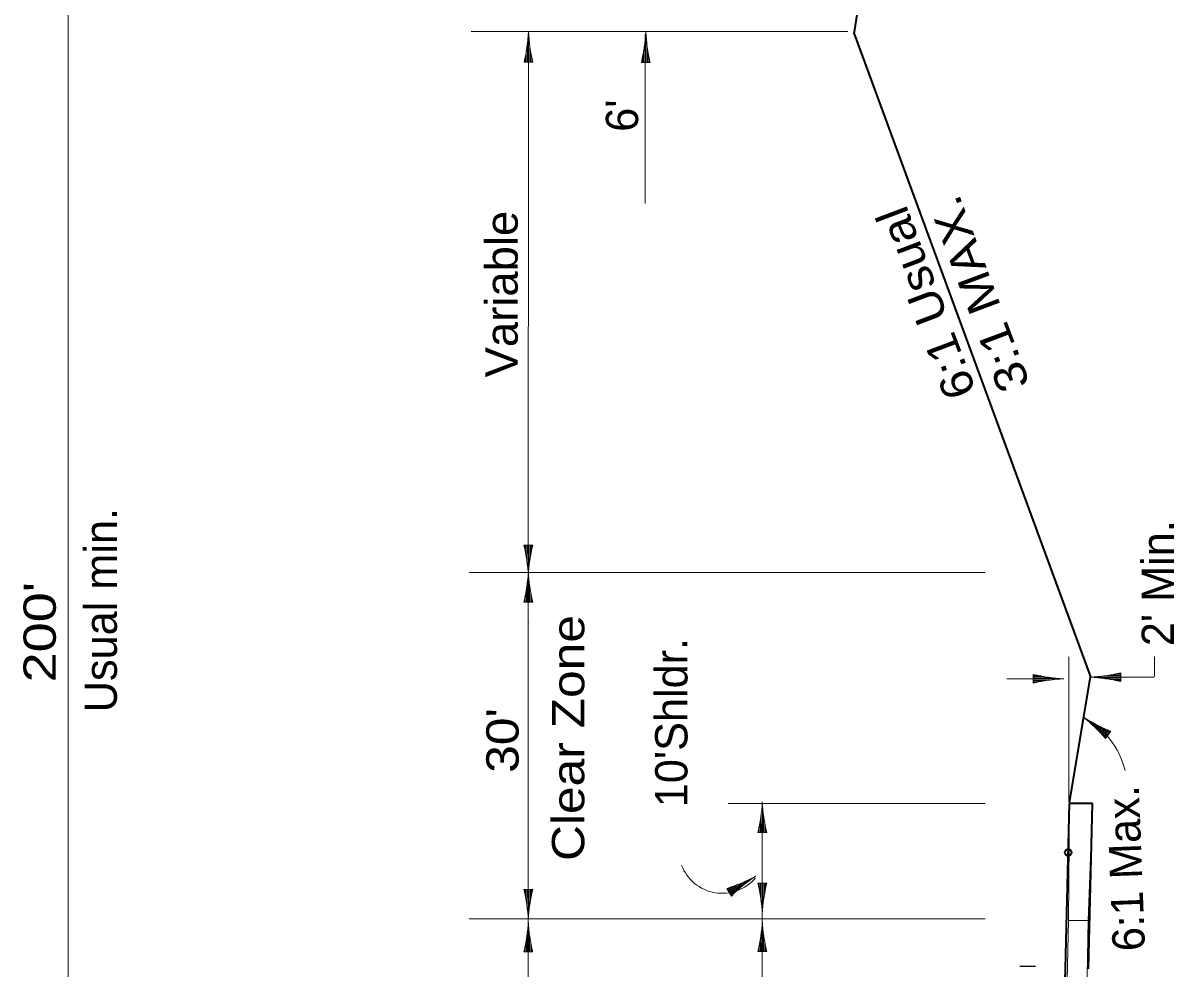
# Model space of a CAD drawing. Extents: x 2363427 to 2368559, y 6957299 to 6980140.
# Drawn here: x 2363668.7 to 2364167.1, y 6961810.7 to 6962220.2 of the extents above; entities that cross this region are included whole.
import ezdxf
from ezdxf.enums import TextEntityAlignment as Align

# ---------------------------------------------------------------- set-up
doc = ezdxf.new("R2010")
doc.units = 0
doc.header["$LTSCALE"] = 5.6
doc.header["$PDMODE"] = 32
doc.header["$PDSIZE"] = 2.8
for name, color, linetype, lineweight in [('3', 7, 'Continuous', 35), ('4', 7, 'Continuous', 13), ('48', 7, 'Continuous', 25)]:
    doc.layers.add(name, color=color, linetype=linetype, lineweight=lineweight)

msp = doc.modelspace()

# ---------------------------------------------------------------- linework, layer by layer
at = {"layer": '3'}
for p, q in [((2364028.519, 6962215.437), (2364033.505, 6962246.281)), ((2364028.519, 6962215.437), (2364130.866, 6961937.19)), ((2364121.845, 6961882.668), (2364130.866, 6961937.19)), ((2364120.086, 6961810.917), (2364121.751, 6961882.347)), ((2364131.755, 6961882.347), (2364121.751, 6961882.347)), ((2364130.083, 6961810.683), (2364131.752, 6961882.231)), ((2364121.017, 6961860.969), (2364121.255, 6961861.068))]:
    msp.add_line(p, q, dxfattribs=at)
at = {"layer": '3', "lineweight": 13}
msp.add_lwpolyline([(2364121.322, 6961831.721), (2364129.856, 6961831.721), (2364131.755, 6961882.347), (2364121.751, 6961882.347)], close=True, dxfattribs=at)
at = {"layer": '3'}
msp.add_lwpolyline([(2364111.676, 6961377.102), (2364116.953, 6961691.051), (2364120.086, 6961810.917)], dxfattribs=at)
msp.add_point((2364121.255, 6961861.068), dxfattribs=at)
at = {"layer": '4'}
for p, q in [((2363688.134, 6961377.102), (2363688.134, 6962511.097)), ((2364025.901, 6962216.508), (2363862.717, 6962216.508)), ((2363887.459, 6961961.097), (2363887.535, 6962216.508)), ((2363887.596, 6962203.196), (2363887.6, 6962215.76)), ((2363887.596, 6962203.196), (2363887.6, 6962215.76)), ((2363938.134, 6962142.008), (2363938.134, 6962215.267)), ((2363938.393, 6962203.111), (2363938.393, 6962215.675)), ((2363886.596, 6962203.196), (2363886.597, 6962208.058)), ((2363886.596, 6962203.196), (2363886.597, 6962208.058)), ((2363887.096, 6962203.196), (2363887.099, 6962211.806)), ((2363887.096, 6962203.196), (2363887.099, 6962211.806)), ((2363888.096, 6962203.196), (2363888.099, 6962210.546)), ((2363888.096, 6962203.196), (2363888.099, 6962210.546)), ((2363888.596, 6962203.196), (2363888.597, 6962207.472)), ((2363888.596, 6962203.196), (2363888.597, 6962207.472)), ((2363937.393, 6962203.111), (2363937.393, 6962207.973)), ((2363937.893, 6962203.111), (2363937.893, 6962211.72)), ((2363938.893, 6962203.111), (2363938.893, 6962210.461)), ((2363939.393, 6962203.111), (2363939.393, 6962207.387)), ((2363889.446, 6962203.196), (2363885.616, 6962203.196)), ((2363889.446, 6962203.196), (2363885.616, 6962203.196)), ((2363886.096, 6962203.196), (2363886.097, 6962205.578)), ((2363886.096, 6962203.196), (2363886.097, 6962205.578)), ((2363889.096, 6962203.196), (2363889.097, 6962204.78)), ((2363889.096, 6962203.196), (2363889.097, 6962204.78)), ((2363940.243, 6962203.111), (2363936.413, 6962203.111)), ((2363936.893, 6962203.111), (2363936.893, 6962205.492)), ((2363939.893, 6962203.111), (2363939.893, 6962204.695)), ((2363885.547, 6961994.152), (2363889.377, 6961994.151)), ((2363885.897, 6961994.152), (2363885.897, 6961992.567)), ((2363886.397, 6961994.152), (2363886.396, 6961989.875)), ((2363886.897, 6961994.151), (2363886.895, 6961986.802)), ((2363887.397, 6961994.151), (2363887.393, 6961981.587)), ((2363887.897, 6961994.151), (2363887.895, 6961985.541)), ((2363888.397, 6961994.151), (2363888.396, 6961989.289)), ((2363888.897, 6961994.151), (2363888.897, 6961991.769)), ((2364085.251, 6961982.347), (2363861.855, 6961982.347)), ((2363887.023, 6961969.513), (2363887.023, 6961978.122)), ((2363887.523, 6961969.513), (2363887.523, 6961982.077)), ((2363886.523, 6961969.513), (2363886.523, 6961974.375)), ((2363888.023, 6961969.513), (2363888.023, 6961976.863)), ((2363888.523, 6961969.513), (2363888.523, 6961973.789)), ((2363889.373, 6961969.513), (2363885.543, 6961969.513)), ((2363886.023, 6961969.513), (2363886.023, 6961971.894)), ((2363889.023, 6961969.513), (2363889.023, 6961971.097)), ((2363887.536, 6961960.669), (2363887.459, 6961961.097)), ((2364121.589, 6961882.873), (2364121.589, 6961945.809)), ((2364158.594, 6961937.315), (2364158.594, 6961945.959)), ((2364106.057, 6961934.384), (2364106.057, 6961938.214)), ((2364106.057, 6961934.384), (2364106.057, 6961938.214)), ((2364106.057, 6961937.734), (2364108.439, 6961937.734)), ((2364106.057, 6961937.734), (2364108.439, 6961937.734)), ((2364144.063, 6961938.031), (2364139.787, 6961938.031)), ((2364144.063, 6961938.531), (2364142.479, 6961938.531)), ((2364144.063, 6961938.881), (2364144.063, 6961935.051)), ((2364119.369, 6961936.299), (2364094.666, 6961936.299)), ((2364106.057, 6961937.234), (2364110.919, 6961937.234)), ((2364106.057, 6961937.234), (2364110.919, 6961937.234)), ((2364106.057, 6961936.734), (2364114.667, 6961936.734)), ((2364106.057, 6961936.734), (2364114.667, 6961936.734)), ((2364106.057, 6961936.234), (2364118.621, 6961936.234)), ((2364106.057, 6961936.234), (2364118.621, 6961936.234)), ((2364106.057, 6961935.734), (2364113.407, 6961935.734)), ((2364106.057, 6961935.734), (2364113.407, 6961935.734)), ((2364106.057, 6961935.234), (2364110.334, 6961935.234)), ((2364106.057, 6961935.234), (2364110.334, 6961935.234)), ((2364106.057, 6961934.734), (2364107.643, 6961934.734)), ((2364106.057, 6961934.734), (2364107.643, 6961934.734)), ((2364144.063, 6961937.031), (2364131.499, 6961937.031)), ((2364131.931, 6961936.967), (2364158.509, 6961936.967)), ((2364144.063, 6961936.531), (2364135.454, 6961936.531)), ((2364144.063, 6961937.531), (2364136.713, 6961937.531)), ((2364144.063, 6961936.031), (2364139.201, 6961936.031)), ((2364144.063, 6961935.531), (2364141.682, 6961935.531)), ((2364138.597, 6961912.088), (2364128.355, 6961919.367)), ((2364138.307, 6961911.681), (2364131.289, 6961916.669)), ((2364138.886, 6961912.495), (2364132.895, 6961916.753)), ((2364138.017, 6961911.273), (2364134.054, 6961914.089)), ((2364139.175, 6961912.903), (2364135.691, 6961915.381)), ((2364139.668, 6961913.596), (2364137.449, 6961910.474)), ((2364139.465, 6961913.311), (2364138.173, 6961914.229)), ((2364137.727, 6961910.865), (2364135.786, 6961912.245)), ((2364085.251, 6961882.347), (2363973.971, 6961882.347)), ((2363988.341, 6961869.718), (2363988.341, 6961878.327)), ((2363988.841, 6961869.718), (2363988.841, 6961882.282)), ((2363987.841, 6961869.718), (2363987.841, 6961874.58)), ((2363988.775, 6961823.369), (2363988.775, 6961873.397)), ((2363989.341, 6961869.718), (2363989.341, 6961877.068)), ((2363989.841, 6961869.718), (2363989.841, 6961873.995)), ((2363990.691, 6961869.718), (2363986.861, 6961869.718)), ((2363987.341, 6961869.718), (2363987.341, 6961872.099)), ((2363990.341, 6961869.718), (2363990.341, 6961871.303)), ((2363974.207, 6961844.261), (2363981.567, 6961848.729)), ((2363974.467, 6961843.834), (2363985.207, 6961850.353)), ((2363885.547, 6961845.139), (2363889.377, 6961845.137)), ((2363885.897, 6961845.139), (2363885.897, 6961843.553)), ((2363886.397, 6961845.139), (2363886.396, 6961840.862)), ((2363886.897, 6961845.138), (2363886.895, 6961837.789)), ((2363887.397, 6961845.138), (2363887.393, 6961832.574)), ((2363887.897, 6961845.138), (2363887.895, 6961836.528)), ((2363888.397, 6961845.138), (2363888.396, 6961840.276)), ((2363888.897, 6961845.137), (2363888.897, 6961842.756)), ((2363975.427, 6961842.253), (2363973.439, 6961845.527)), ((2363973.689, 6961845.116), (2363975.725, 6961846.352)), ((2363973.949, 6961844.689), (2363978.105, 6961847.211)), ((2363974.727, 6961843.407), (2363981.009, 6961847.221)), ((2363974.986, 6961842.979), (2363978.642, 6961845.198)), ((2363975.245, 6961842.552), (2363976.601, 6961843.375)), ((2363986.861, 6961847.809), (2363990.691, 6961847.809)), ((2363987.211, 6961847.809), (2363987.211, 6961846.223)), ((2363987.711, 6961847.809), (2363987.711, 6961843.532)), ((2363988.211, 6961847.809), (2363988.211, 6961840.459)), ((2363988.711, 6961847.809), (2363988.711, 6961835.245)), ((2363989.211, 6961847.809), (2363989.211, 6961839.199)), ((2363989.711, 6961847.809), (2363989.711, 6961842.947)), ((2363990.211, 6961847.809), (2363990.211, 6961845.427)), ((2364085.251, 6961832.347), (2363861.855, 6961832.347)), ((2363887.523, 6961818.035), (2363887.523, 6961830.599)), ((2363988.841, 6961818.195), (2363988.841, 6961830.759)), ((2363887.023, 6961818.035), (2363887.023, 6961826.644)), ((2363888.023, 6961818.035), (2363888.023, 6961825.385)), ((2363988.341, 6961818.195), (2363988.341, 6961826.804)), ((2363989.341, 6961818.195), (2363989.341, 6961825.545)), ((2363886.023, 6961818.035), (2363886.023, 6961820.416)), ((2363886.523, 6961818.035), (2363886.523, 6961822.897)), ((2363888.523, 6961818.035), (2363888.523, 6961822.311)), ((2363889.023, 6961818.035), (2363889.023, 6961819.619)), ((2363990.691, 6961818.195), (2363986.861, 6961818.195)), ((2363987.341, 6961818.195), (2363987.341, 6961820.576)), ((2363987.841, 6961818.195), (2363987.841, 6961823.057)), ((2363988.775, 6961702.079), (2363988.775, 6961822.051)), ((2363989.841, 6961818.195), (2363989.841, 6961822.471)), ((2363990.341, 6961818.195), (2363990.341, 6961819.779)), ((2363889.373, 6961818.035), (2363885.543, 6961818.035))]:
    msp.add_line(p, q, dxfattribs=at)
at = {"layer": '4', "lineweight": 25}
msp.add_line((2364100.31, 6961811.918), (2364107.149, 6961811.918), dxfattribs=at)
at = {"layer": '4'}
msp.add_lwpolyline([(2363887.459, 6961592.347), (2363887.459, 6961811.069), (2363887.459, 6961961.097)], dxfattribs=at)
for centre, radius, start, end in [((2363815.413, 6962220.112), 72.212, 346.45333, 357.13938), ((2363815.413, 6962220.112), 72.212, 346.45333, 357.13938), ((2363959.66, 6962220.069), 72.212, 182.82649, 193.51254), ((2363959.66, 6962220.069), 72.212, 182.82649, 193.51254), ((2363866.204, 6962220.005), 72.212, 346.47039, 357.15644), ((2364010.451, 6962220.005), 72.212, 182.84356, 193.52961), ((2363815.334, 6961977.28), 72.212, 2.82649, 13.51254), ((2363959.581, 6961977.237), 72.212, 166.45333, 177.13938), ((2363815.335, 6961986.407), 72.212, 346.47039, 357.15644), ((2363959.582, 6961986.407), 72.212, 182.84356, 193.52961), ((2364122.951, 6962008.423), 72.212, 256.47039, 267.15644), ((2364122.951, 6962008.423), 72.212, 256.47039, 267.15644), ((2364127.17, 6962009.091), 72.212, 272.84356, 283.52961), ((2364122.951, 6961864.176), 72.212, 92.84356, 103.52961), ((2364122.951, 6961864.176), 72.212, 92.84356, 103.52961), ((2364127.17, 6961864.844), 72.212, 76.47039, 87.15644), ((2364111.918, 6961888.476), 34.94, 13.44028, 63.14536), ((2364166.576, 6961980.608), 72.212, 237.43652, 248.12257), ((2364083.002, 6961863.038), 72.212, 41.06336, 51.74941), ((2363916.652, 6961886.612), 72.212, 346.47039, 357.15644), ((2364060.899, 6961886.612), 72.212, 182.84356, 193.52961), ((2363971.434, 6961862.255), 18.823, 200.84978, 319.74384), ((2363951.448, 6961914.309), 72.212, 287.73061, 298.41666), ((2364026.301, 6961791.004), 72.212, 124.10378, 134.78983), ((2363815.334, 6961828.266), 72.212, 2.82649, 13.51254), ((2363959.581, 6961828.223), 72.212, 166.45333, 177.13938), ((2363916.652, 6961830.915), 72.212, 2.84356, 13.52961), ((2364060.899, 6961830.915), 72.212, 166.47039, 177.15644), ((2363815.335, 6961834.929), 72.212, 346.47039, 357.15644), ((2363959.582, 6961834.929), 72.212, 182.84356, 193.52961), ((2363916.652, 6961835.089), 72.212, 346.47039, 357.15644), ((2364060.899, 6961835.089), 72.212, 182.84356, 193.52961)]:
    msp.add_arc(centre, radius, start, end, dxfattribs=at)
at = {"layer": '48', "lineweight": 13}
msp.add_lwpolyline([(2364115.988, 6961591.851), (2364125.589, 6961591.851), (2364129.856, 6961831.721), (2364121.322, 6961831.721)], close=True, dxfattribs=at)

# ---------------------------------------------------------------- texts
at = {"layer": '4'}
for s, rotation, p in [("6' ", 90, (2363935.023, 6962182.666)), ('Usual min.', 90, (2363709.295, 6961966.014)), ("2' Min.", 90, (2364167.068, 6961977.667)), ("10'Shldr.", 90, (2363956.388, 6961917.333)), ('6:1 Max.', 92.174, (2364153.189, 6961854.473))]:
    msp.add_text(s, height=14, rotation=rotation, dxfattribs=at).set_placement(p, align=Align.CENTER)
for s, rotation, width, p in [('3:1 MAX.', 110.58, 1.15, (2364089.313, 6962105.299)), ('Variable', 90, 1.05, (2363882.874, 6962102.823)), ('6:1 Usual', 110.701, 1.1, (2364066.234, 6962101.357)), ("200'", 90, 1.25, (2363682.859, 6961956.471)), ('Clear Zone', 90, 1.15, (2363911.704, 6961910.652)), ("30'", 90, 1.15, (2363883.264, 6961909.607))]:
    msp.add_text(s, height=14, rotation=rotation, dxfattribs=dict(at, width=width)).set_placement(p, align=Align.CENTER)

doc.saveas('drawing.dxf')
